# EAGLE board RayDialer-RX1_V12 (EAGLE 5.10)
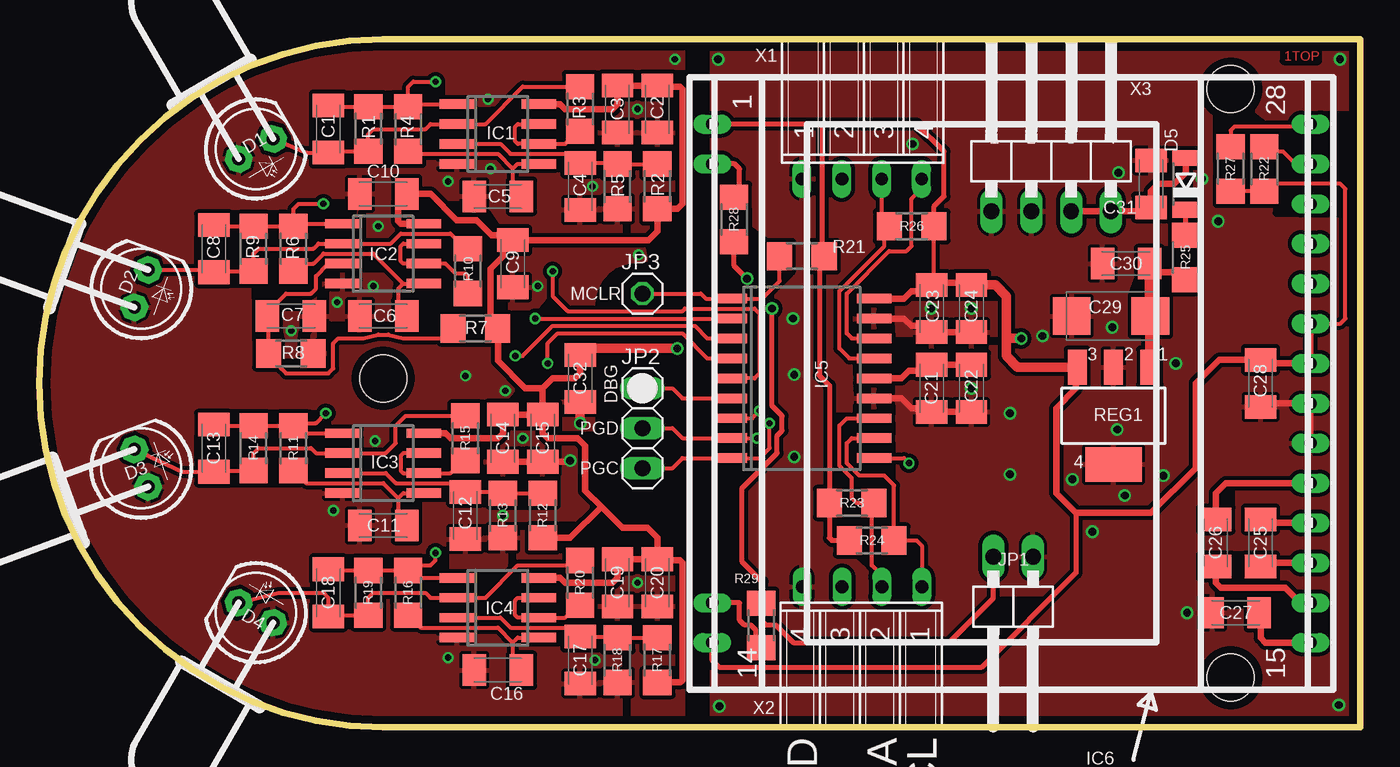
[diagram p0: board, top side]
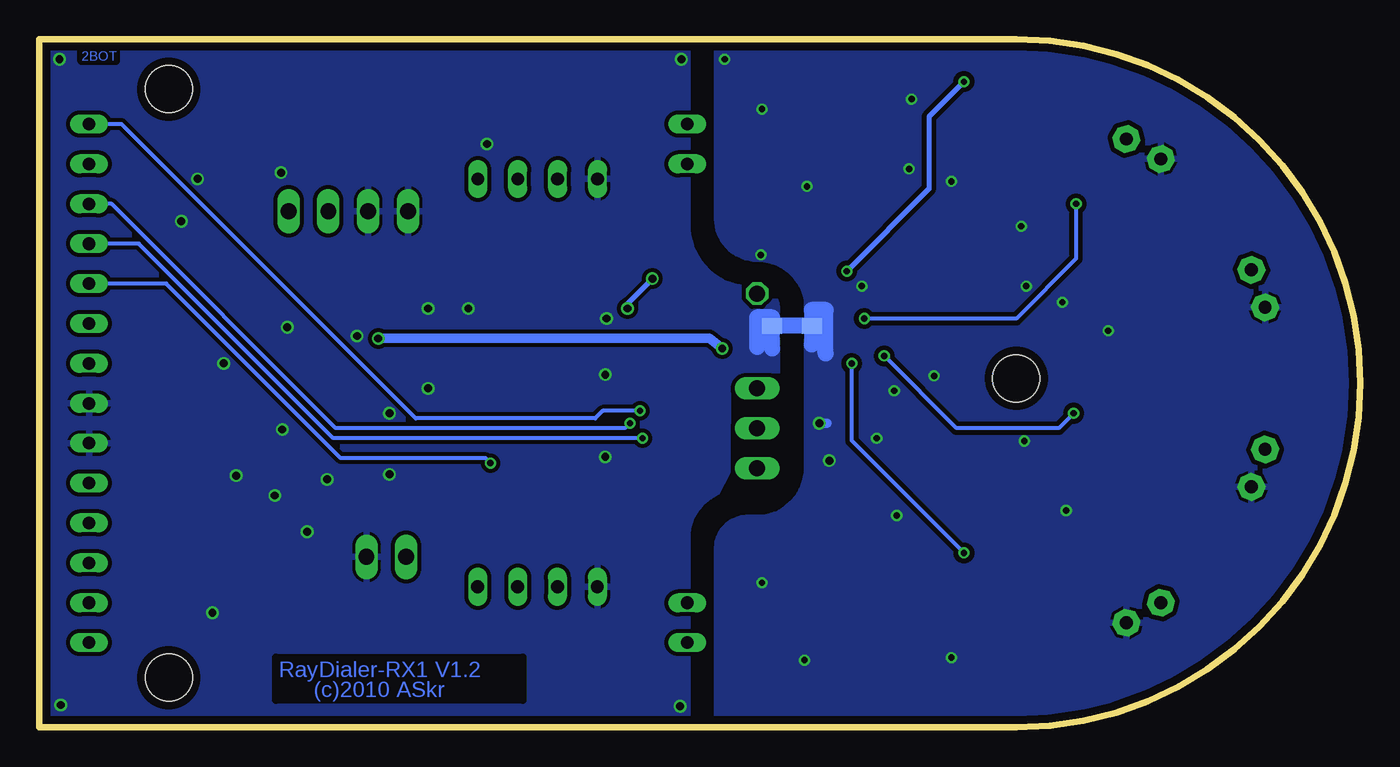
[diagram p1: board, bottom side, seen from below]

Size 84.14 x 43.81 mm. Coordinates in mm from the lower left corner, seen from the top.
Outline: 21.91,0 84.14,0 84.14,43.81 21.91,43.81 arc180 21.91,0
Copper layers (1*16): Top 0.035mm / dielectric 1.5mm / Bottom 0.035mm
Design rules "pcb-pool-2009": minimum track width 6mil, minimum drill 12mil, track to track 6mil, track to pad 6mil, pad to pad 6mil, via to via 6mil, smd to smd 6mil, copper to edge 20mil, drill to drill 8mil, minimum pad ring 8mil, minimum via ring 6mil, stop-mask expansion 3mil, vias tented up to drill 0mil, thermal gap 8mil
Holes 3 mm at 21.91,22.23 75.88,3.17 75.88,40.64
tRestrict: 111 lines
bRestrict: 11 lines

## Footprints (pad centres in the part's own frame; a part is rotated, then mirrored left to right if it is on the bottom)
C1206K = smd 1.5 x 2: 1 -1.5,0; 2 1.5,0
SMC_C = smd 2.4 x 2.4: + -2.5,0; - 2.5,0
AKKI_PHOTODIODE5MM = drill 0.813 pad 1.676 octagon: A -1.27,0; K 1.27,0
SOD80-R = smd 1 x 1.7: A 1.65,0; C -1.65,0
SO08 = smd 0.6 x 2.2: 1 -1.905,-2.6; 2 -0.635,-2.6; 3 0.635,-2.6; 4 1.905,-2.6; 5 1.905,2.6; 6 0.635,2.6; 7 -0.635,2.6; 8 -1.905,2.6
AKKI_SO18W = smd 0.6 x 2.2: 1 -5.715,-4.6; 2 -4.445,-4.6; 3 -3.175,-4.6; 4 -1.905,-4.6; 5 -0.635,-4.6; 6 0.635,-4.6; 7 1.905,-4.6; 8 3.175,-4.6; 9 4.445,-4.6; 10 4.445,4.6; 11 3.175,4.6; 12 1.905,4.6; 13 0.635,4.6; 14 -0.635,4.6; 15 -1.905,4.6; 16 -3.175,4.6; 17 -4.445,4.6; 18 -5.715,4.6
AKKI_EA_DOGS102 = drill 0.8 long: 1 -16.51,-19.05; 2 -13.97,-19.05; 13 13.97,-19.05; 14 16.51,-19.05; 15 16.51,19.05; 16 13.97,19.05; 17 11.43,19.05; 18 8.89,19.05; 19 6.35,19.05; 20 3.81,19.05; 21 1.27,19.05; 22 -1.27,19.05; 23 -3.81,19.05; 24 -6.35,19.05; 25 -8.89,19.05; 26 -11.43,19.05; 27 -13.97,19.05; 28 -16.51,19.05
1X02/90 = drill 1.016 long: 1 -1.27,-3.81; 2 1.27,-3.81
1X03 = drill 1.016 long: 1 -2.54,0; 2 0,0; 3 2.54,0
1X01 = drill 1.016 octagon: 1 0,0
R1206 = smd 1.6 x 1.803: 1 -1.422,0; 2 1.422,0
AKKI_SOT223_4PIN = smd 1.219 x 2.235: 1 -2.311,-3.099; 2 0,-3.099; 3 2.311,-3.099 | smd 3.6 x 2.2: 4 0,3.099
AKKI_GNDCON40 = smd 1.27 x 1.016: P$1 -1.27,0; P$2 1.27,0
AKKI_FH1X4 = drill 0.813 long: 1 -5.08,0; 2 -2.54,0; 3 0,0; 4 2.54,0
1X04/90 = drill 1.016 long: 1 -3.81,-3.81; 2 -1.27,-3.81; 3 1.27,-3.81; 4 3.81,-3.81

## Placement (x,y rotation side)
C1  1p  [C1206K]  18.41,38.1 90 top
C2  1u  [C1206K]  39.37,39.37 90 top
C3  100n  [C1206K]  36.83,39.37 90 top
C4  1u  [C1206K]  34.45,34.45 270 top
C5  10u  [C1206K]  29.21,33.81 180 top
C6  10u  [C1206K]  21.91,26.19 180 top
C7  1u  [C1206K]  16.03,26.19 0 top
C8  1p  [C1206K]  11.11,30.48 90 top
C9  100n  [C1206K]  30.16,29.53 90 top
C10  1u  [C1206K]  21.91,33.97 0 top
C11  10u  [C1206K]  21.91,12.86 180 top
C12  1u  [C1206K]  27.15,13.49 270 top
C13  1p  [C1206K]  11.11,17.78 90 top
C14  100n  [C1206K]  29.53,18.41 90 top
C15  1u  [C1206K]  32.07,18.41 90 top
C16  10u  [C1206K]  29.21,3.65 180 top
C17  1u  [C1206K]  34.45,4.29 270 top
C18  1p  [C1206K]  18.41,8.57 90 top
C19  100n  [C1206K]  36.83,9.21 90 top
C20  1u  [C1206K]  39.37,9.21 90 top
C21  10u  [C1206K]  56.83,21.59 270 top
C22  100n  [C1206K]  59.37,21.59 270 top
C23  1u  [C1206K]  56.83,26.67 270 top
C24  100n  [C1206K]  59.37,26.67 270 top
C25  1u  [C1206K]  77.79,11.75 90 top
C26  1u  [C1206K]  74.93,11.75 90 top
C27  1u  [C1206K]  76.2,7.3 180 top
C28  1u  [C1206K]  77.79,21.91 270 top
C29  22u;6V3  [SMC_C]  68.26,26.19 180 top
C30  100n  [C1206K]  69.22,29.53 180 top
C31  100n  [C1206K]  70.8,34.61 90 top
C32  100n  [C1206K]  34.45,22.23 270 top
D1  SFH203FA  [AKKI_PHOTODIODE5MM]  13.8,36.83 30 top
D2  SFH203FA  [AKKI_PHOTODIODE5MM]  6.5,27.94 70 top
D3  SFH203FA  [AKKI_PHOTODIODE5MM]  6.5,16.51 110 top
D4  SFH203FA  [AKKI_PHOTODIODE5MM]  13.8,7.3 150 top
D5  LL103  [SOD80-R]  73.03,34.61 90 top
IC1  MCP602SN  [SO08]  29.21,37.78 270 top
IC2  MCP602SN  [SO08]  21.91,30.16 270 top
IC3  MCP602SN  [SO08]  21.91,16.83 270 top
IC4  MCP602SN  [SO08]  29.21,7.62 270 top
IC5  DSPIC33FJ12GP201  [AKKI_SO18W]  48.58,21.59 270 top
IC6  EA_DOGS102  [AKKI_EA_DOGS102]  61.91,21.91 270 top
JP1  [1X02/90]  62.03,7.04 180 top
JP2  [1X03]  38.42,19.05 270 top
JP3  [1X01]  38.42,27.62 0 top
R1  4M7  [R1206]  20.95,38.1 270 top
R2  100k  [R1206]  39.37,34.45 270 top
R3  22k  [R1206]  34.45,39.37 270 top
R4  1M  [R1206]  23.49,38.1 90 top
R5  100k  [R1206]  36.83,34.45 90 top
R6  1M  [R1206]  16.19,30.48 90 top
R7  100k  [R1206]  27.78,25.4 0 top
R8  100k  [R1206]  16.03,23.81 180 top
R9  4M7  [R1206]  13.65,30.48 270 top
R10  22k  [R1206]  27.3,29.05 270 top
R11  1M  [R1206]  16.19,17.78 90 top
R12  100k  [R1206]  32.07,13.49 270 top
R13  100k  [R1206]  29.53,13.49 90 top
R14  4M7  [R1206]  13.65,17.78 270 top
R15  22k  [R1206]  27.15,18.42 270 top
R16  1M  [R1206]  23.49,8.57 90 top
R17  100k  [R1206]  39.37,4.29 270 top
R18  100k  [R1206]  36.83,4.29 90 top
R19  4M7  [R1206]  20.95,8.57 270 top
R20  22k  [R1206]  34.45,9.21 270 top
R21  10k  [R1206]  48.58,30 0 top
R22  10k  [R1206]  78.03,35.56 90 top
R23  82k  [R1206]  51.75,14.29 180 top
R24  82k  [R1206]  53.02,11.91 180 top
R25  1E  [R1206]  73.03,29.92 90 top
R26  100k  [R1206]  55.56,31.91 180 top
R27  100k  [R1206]  75.88,35.56 270 top
R28  100E  [R1206]  44.25,32.35 90 top
R29  100E  [R1206]  45.98,6.49 270 top
REG1  MCP1703-33  [AKKI_SOT223_4PIN]  68.42,19.84 180 top
W1  GNDCON  [AKKI_GNDCON40]  36.2,25.56 180 bottom
X1  [AKKI_FH1X4]  53.66,34.92 0 top
X2  [AKKI_FH1X4]  51.13,8.96 180 top
X3  [1X04/90]  64.45,36.67 0 top

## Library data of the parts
C1-C28 C30-C32 = rcl
C29 = rcl; SIZE: "C"; TYPE: TANT
D1-D5 IC5 IC6 R1-R29 REG1 W1 X1 X2 = Akki
IC1-IC4 = linear
JP1-JP3 X3 = pinhead

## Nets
+3V3: C2.2 C3.2 C9.2 C10.2 C14.2 C15.2 C19.2 C20.2 C23.1 C24.1 C28.1 C32.1 IC1.8 IC2.8 IC3.8 IC4.8 IC5.18 IC6.1 IC6.14 IC6.22 IC6.23 R2.2 R7.2 R12.2 R17.2 R21.2 R22.1 R23.2 R24.2 R26.1 R27.2 REG1.3
AGND: C2.1 C3.1 C4.2 C5.2 C6.2 C7.2 C9.1 C10.1 C11.2 C12.2 C14.1 C15.1 C16.2 C17.2 C19.1 C20.1 C32.2 D1.A D2.A D3.A D4.A IC1.4 IC2.4 IC3.4 IC4.4 R5.1 R8.1 R13.1 R18.1 W1.P$1
CD: IC5.9 IC6.26 JP2.3
CH1: C18.2 IC4.1 IC5.4 R16.2 R19.1
CH2: C13.2 IC3.1 IC5.3 R11.2 R14.1
CH3: C8.2 IC2.1 IC5.2 R6.2 R9.1
CH4: C1.2 IC1.1 IC5.5 R1.1 R4.2
CS0: IC5.7 IC6.28 R27.1
GND: C21.2 C22.2 C23.2 C24.2 C27.2 C28.2 C29.- C30.2 C31.2 IC5.13 IC5.17 IC6.20 IC6.21 JP1.1 REG1.2 REG1.4 W1.P$2 X1.1 X2.4 X3.1 X3.2
N$1: IC6.27 R22.2
N$2: IC6.13 R29.2
N$3: C21.1 C22.1 IC5.14
N$4: IC5.1 JP3.1 R21.1
N$5: C27.1 IC6.15
N$6: C25.1 IC6.17
N$7: C25.2 IC6.18
N$8: C26.2 IC6.19
N$9: C26.1 IC6.16
N$10: IC5.6 JP2.1
N$11: D5.C R25.2
N$12: IC6.2 R28.2
N$13: C29.+ C30.1 R25.1 REG1.1
N$14: JP1.2 R28.1 R29.1
N$15: C31.1 D5.A X3.3 X3.4
RX: IC5.15 R26.2 X1.3
SCK: IC5.8 IC6.25 JP2.2
SCL: IC5.11 R24.1 X2.1
SDA: IC5.12 R23.1 X2.2
SO: IC5.10 IC6.24
TX: IC5.16 X1.4
UN: C1.1 D1.K IC1.2 R1.2 R3.1
UN1: C8.1 D2.K IC2.2 R9.2 R10.1
UN2: C13.1 D3.K IC3.2 R14.2 R15.1
UN3: C18.1 D4.K IC4.2 R19.2 R20.1
UO2: IC1.6 IC1.7 R3.2
UO4: IC2.6 IC2.7 R10.2
UO6: IC3.6 IC3.7 R15.2
UO8: IC4.6 IC4.7 R20.2
UP: C4.1 IC1.3 R2.1 R5.2
UP1: C6.1 IC2.5 R6.1
UP2: C5.1 IC1.5 R4.1
UP3: C7.1 IC2.3 R7.1 R8.2
UP4: C11.1 IC3.5 R11.1
UP5: C12.1 IC3.3 R12.1 R13.2
UP6: C16.1 IC4.5 R16.1
UP7: C17.1 IC4.3 R17.1 R18.2

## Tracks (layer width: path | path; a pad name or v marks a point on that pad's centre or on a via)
+3V3  (via drill 0.5, 0.5 pad 0.5)
  Top 0.254: R26.1 56.98,28.32 C23.1 | IC6.23 82.87,25.72 83.18,26.04 83.18,34.29 82.87,34.61 78.5,34.61 R22.1 R27.2 | R27.2
  Top 0.305: R24.2 50.48,11.91 50.32,12.06 R23.2 50.33,21.76 49.69,22.4 49.69,29.37 50,29.68 | 49.85,38.42 55.88,38.42 57.63,36.67 57.63,33.81 56.99,33.18 R26.1 | 49.85,38.42 IC6.1 | IC6.14 42.86,4.29 43.34,3.81 60.01,3.81 66.04,9.84 66.04,13.65 | 50,29.68 R21.2 | 50,29.68 49.85,29.83 49.85,38.42
  Top 0.406: IC1.8 33.18,39.69 33.5,39.37 36.51,39.37 36.83,39.69 C3.2 C2.2 39.44,40.8 40.8,40.8 40.96,40.64 40.96,33.34 40.65,33.03 R2.2 | 29.81,31.2 29.53,31.34 28.82,31.34 27.86,32.31 26.59,32.31 24.92,33.97 C10.2 22.86,33.42 22.86,32.23 23.02,32.07 IC2.8 | 29.81,31.2 C9.2 38.81,31.03 39.37,31.59 R2.2 | IC3.8 25.88,18.73 26.19,18.41 29.21,18.41 29.53,18.73 C14.2 | C14.2 | C15.2 C14.2 | IC4.8 33.18,9.53 33.5,9.21 36.51,9.21 36.83,9.53 C19.2 C20.2 | IC5.18 55.09,27.3 55.56,27.78 56.44,27.78 C23.1 | 56.98,28.32 59.22,28.32 C24.1 | IC6.23 IC6.22 78.02,23.18 C28.1 75.16,23.41 73.66,21.91 73.66,16.51 70.8,13.65 66.04,13.65 64.77,14.92 64.77,20.32 66.04,21.59 66.04,23.35 REG1.3 | R17.2 40.81,2.86 40.96,3.02 40.96,10.48 40.8,10.64 39.44,10.64 C20.2 | C20.2 39.37,12.06 38.74,12.7 37.15,12.7 35.8,14.05 | 35.8,14.05 34.77,15.08 34.77,17.94 34.29,18.41 32.39,18.41 32.07,18.73 C15.2 | C15.2 32.14,19.84 | C15.2 32.07,21.59 | 32.07,21.59 30.96,21.59 29.21,23.34 R7.2 28.73,25.87 28.73,29.21 29.53,30 29.53,30.64 29.81,30.92 29.81,31.2 | R2.2 | C15.2 | 32.07,21.59 32.7,22.23 34.13,22.23 34.45,22.54 C32.1 | R12.2 33.82,12.07 35.8,14.05
  Top 0.61: C24.1 60.89,28.17 61.6,27.46 61.6,24.77 | v62.55,24.77 61.6,24.77 | v40.64,24.13 34.7,24.13 arc90 C32.1 | 61.6,24.77 61.6,23.65 62.31,22.94 REG1.3
  Bottom 0.61: v62.55,24.77 41.43,24.77 v40.64,24.13
AGND  (via drill 0.4 pad 0.5, 0.5 pad 0.5)
  Top 0.406: v33.81,16.99 33.74,16.91 C15.1 C14.1
  Top 0.61: v34.45,19.37 C32.2
  Bottom 0.406: v33.81,16.99 33.81,17.14
  Bottom 0.61: v34.45,19.37 33.97,19.37
  Bottom 1.016: 34.92,24.37 W1.P$1 34.92,26.59 34.05,26.59 34.05,23.81
  other vias: 38.1,9.21 26.03,4.45 35.4,4.29 18.73,13.81 21.27,28.1 29.69,21.43 27.15,22.38 21.39,18.24 26.03,34.77 38.1,39.37 35.24,34.45 31.75,28.1 30.8,18.41 29.53,13.49 21.59,31.91 28.73,35.56 40.48,42.55 28.57,40.01 18.97,27.07 38.18,30.08 16.05,25.26
  pour Bottom (isolate 0.305): 40.96,45.09 40.96,32.38 arc-90 38.42,29.84 arc77 35.24,27.3 35.24,16.51 arc90 38.42,13.34 39.05,13.34 arc-90 40.96,11.43 40.96,-1.27 -2.86,-1.27 -2.86,45.09
  pour Top (isolate 0.254): 40.96,45.09 40.96,33.02 arc-90 39.05,29.84 38.1,29.69 arc90 35.24,26.99 35.24,15.88 37.78,13.34 39.05,13.34 40.96,11.43 40.96,-1.27 -1.59,-1.27 -1.59,45.09
CD  (via drill 0.4)
  Top 0.254: v46.51,19.37 46.51,17.78 45.88,17.14 IC5.9 40.96,17.14 40.32,16.51 JP2.3
  Bottom 0.254: v46.51,19.37 46.83,19.05 65.25,19.05 79.53,33.34 IC6.26
CH1  (via drill 0.4)
  Top 0.254: C18.2 18.49,9.99 R19.1 R16.2 | R16.2 23.96,9.53 IC4.1 | IC5.4 42.54,23.5 40.96,25.08 33.02,25.08 32.39,24.45 v32.39,23.18 | v25.24,11.11 25.24,10.64 24.92,10.32 23.82,10.32 R16.2
  Bottom 0.254: v32.39,23.18 32.39,18.26 v25.24,11.11
CH2  (via drill 0.4)
  Top 0.254: C13.2 11.19,19.2 R14.1 R11.2 | R11.2 16.66,18.73 IC3.1 | IC5.3 42.55,24.77 41.75,25.56 32.7,25.56 30.8,23.65 v30.32,23.65 | v18.26,20 17.62,19.37 16.36,19.37 R11.2
  Bottom 0.254: v30.32,23.65 25.72,19.05 19.21,19.05 v18.26,20
CH3  (via drill 0.4)
  Top 0.254: R6.2 16.66,32.07 IC2.1 | R6.2 R9.1 11.19,31.9 C8.2 | v31.59,26.04 IC5.2 | v18.1,33.34 16.51,33.34 16.19,33.02 R6.2
  Bottom 0.254: v18.1,33.34 18.1,29.84 21.91,26.04 v31.59,26.04
CH4  (via drill 0.4)
  Top 0.254: C1.2 18.49,39.52 R1.1 R4.2 | R4.2 23.33,39.69 IC1.1 | IC5.5 45.56,22.23 45.88,22.54 45.88,26.35 45.56,26.67 41.12,26.67 40.96,26.51 33.65,26.51 32.7,27.46 v32.7,29.05 | v25.24,41.12 23.81,41.12 23.49,40.8 R4.2
  Bottom 0.305: v32.7,29.05 27.46,34.29 27.46,38.89 v25.24,41.12
CS0  (via drill 0.4)
  Top 0.254: IC5.7 45.4,19.68 v45.88,20.16 | R27.1 75.88,38.02 76.12,38.26 80.8,38.26 IC6.28
  Bottom 0.254: v45.88,20.16 48.26,20.16 48.74,19.68 60.17,19.68 78.9,38.42 IC6.28
GND  (via drill 0.5 pad 0.5)
  Top 0.406: C23.2 56.76,25.24 | C23.2 C24.2 | IC5.13 54.93,20.95 55.56,20.32 56.6,20.32 C21.2 C22.2 | IC5.17 55.09,26.04 55.56,25.56 56.44,25.56 C23.2 | C28.2 78.02,20.64 IC6.21 IC6.20
  Bottom 1.016: 37.46,24.13 W1.P$2 37.46,26.11 38.42,26.11 38.42,24.21
  other vias: 59.37,26.67 59.37,21.59 61.83,20 63.9,24.92 68.34,25.48 72.39,23.18 61.83,16.11 73.1,7.3 56.81,26.67 68.66,18.97 65.8,15.8 69.14,14.76 71.6,16.03 67.07,12.46 48,26.04 48.08,22.46 48.08,17.22 43.24,42.55 82.85,42.55 82.77,1.43 43.32,1.35 74.06,34.92 75.09,32.23 55.62,37.15 68.74,35.32
  pour Bottom (isolate 0.254): 42.86,43.18 83.5,43.18 83.5,0.64 42.86,0.64 42.86,12.06 arc90 39.69,15.24 39.05,15.24 arc-90 37.15,17.14 37.15,26.67 arc-90 38.42,27.94 arc90 42.86,31.75
  pour Top (isolate 0.254): 83.5,43.18 42.86,43.18 42.86,32.38 arc-90 38.42,27.94 37.78,27.94 arc90 37.15,27.3 37.15,17.14 arc90 39.05,15.24 39.69,15.24 arc-90 42.86,12.06 42.86,0.64 83.5,0.64
N$1
  Top 0.254: IC6.27 80.01,35.88 79.22,36.67 78.34,36.67 R22.2
N$2
  Top 0.305: IC6.13 44.61,7.94 44.61,6.83 44.93,6.51 45.32,6.51 45.64,6.19 45.64,5.4 R29.2 46.04,5.13
N$3
  Top 0.406: IC5.14 54.93,22.23 55.4,22.7 56.44,22.7 C21.1 C22.1
N$4
  Top 0.254: R21.1 47.15,29.84 47.15,28.42 46.04,27.3 IC5.1 42.47,27.3 42.15,27.62 JP3.1 | JP3.1
N$5
  Top 0.406: IC6.15 78.1,5.4 77.79,5.71 77.79,7.21 C27.1
N$6
  Top 0.406: IC6.17 78.02,10.48 C25.1
N$7
  Top 0.406: IC6.18 78.02,13.02 C25.2
N$8
  Top 0.406: IC6.19 75.56,15.56 74.93,14.92 C26.2
N$9
  Top 0.406: IC6.16 80.33,7.94 79.37,8.89 75.25,8.89 74.93,9.21 C26.1
N$10
  Top 0.254: IC5.6 40.96,20.95 40.32,21.59 JP2.1
N$11
  Top 0.305: R25.2 D5.C | R25.2
N$12
  Top 0.305: IC6.2 44.29,35.88 44.61,35.56 44.61,34.12 R28.2
N$13
  Top 0.406: R25.1 72.78,28.5 72.31,28.97 70.71,28.97
  Top 0.61: C30.1 70.71,28.97 70.71,26.72 C29.+ 70.73,26.64 REG1.1
N$14  (via drill 0.5 pad 0.5)
  Top 0.305: R28.1 44.25,29.41 v45.09,28.57 | v46.67,26.67 46.67,20.48 47.31,19.84 47.31,18.89 46.99,18.57 46.99,17.46 44.77,15.24 44.77,10.56 46.04,9.29 46.04,7.97 | JP1.2 60.76,8.21 57.94,5.4 48.02,5.4 46.91,6.51 46.28,6.51 46.04,6.75 46.04,7.97 | 45.63,8.26 R29.1 46.04,7.97
  Bottom 0.305: v45.09,28.57 46.67,26.99 v46.67,26.67
N$15
  Top 0.305: 70.56,32.86 C31.1 | D5.A
  Top 0.406: X3.3 X3.4 70.56,32.86 | C31.1 70.8,34.13 71.28,34.61 72.31,34.61 73.03,35.32 D5.A
RX
  Top 0.254: IC5.15 51.59,23.5 50.96,24.13 50.96,27.78 53.82,30.64 53.82,31.59 R26.2 53.66,31.91 X1.3
SCK  (via drill 0.4)
  Top 0.254: v45.72,18.41 IC5.8 40.96,18.41 40.32,19.05 JP2.2
  Bottom 0.254: v45.72,18.41 65.4,18.41 77.79,30.8 IC6.25
SCL
  Top 0.254: X2.1 56.21,11.57 55.88,11.91 R24.1 54.44,15.41 53.82,16.03 52.23,16.03 51.43,16.83 51.43,18.1 51.75,18.41 IC5.11
SDA
  Top 0.254: X2.2 53.67,9.67 53.02,10.32 53.02,14.14 R23.1 52.07,14.29 51.75,14.61 51.75,15.88 50.96,16.67 50.96,19.21 51.43,19.68 IC5.12
SO  (via drill 0.4)
  Top 0.254: IC5.10 55.09,17.14 v55.4,16.83
  Bottom 0.254: v55.4,16.83 55.72,17.14 64.93,17.14 76.04,28.26 IC6.24
TX
  Top 0.254: IC5.16 51.75,24.77 51.43,25.08 51.43,27.62 54.13,30.32 55.24,30.32 55.56,30.64 55.56,33.66 56.2,34.29 X1.4
UN
  Top 0.254: D1.K 17.03,36.6 C1.1 18.49,36.68 R1.2 20.96,37.78 21.27,38.1 24.61,38.1 24.92,38.42 IC1.2 28.42,38.42 30.79,40.79 R3.1
UN1
  Top 0.254: D2.K 10.96,29.13 C8.1 11.19,29.06 R9.2 13.65,30.16 13.97,30.48 17.46,30.48 17.78,30.8 IC2.2 22.38,30.8 23.02,31.43 26.19,31.43 26.99,30.64 27.14,30.64 R10.1
UN2
  Top 0.254: D3.K 9.1,16.28 C13.1 11.19,16.36 R14.2 13.65,17.46 13.97,17.78 17.3,17.78 17.62,17.46 IC3.2 22.07,17.46 22.7,18.1 22.7,19.21 23.34,19.84 R15.1
UN3
  Top 0.254: 26.35,8.26 24.92,8.26 24.61,8.57 21.27,8.57 20.96,8.26 R19.2 18.49,7.15 C18.1 18.42,8.26 18.1,8.57 15.24,8.57 D4.K | 26.35,8.26 IC4.2 | R20.1 34.14,10.32 30.48,10.32 28.42,8.26 26.35,8.26 | 26.35,8.26
UO2
  Top 0.254: IC1.7 30.48,38.42 30.32,38.26 30.32,37.31 30.48,37.15 IC1.6 33.5,37.15 33.65,37.31 33.81,37.31 R3.2
UO4
  Top 0.254: IC2.7 23.18,30.8 23.02,30.64 23.02,29.69 23.18,29.53 IC2.6 25.88,29.53 26.51,28.89 27.15,28.89 27.3,28.73 R10.2
UO6
  Top 0.254: IC3.7 23.18,17.46 23.02,17.3 23.02,16.35 23.18,16.19 IC3.6 26.19,16.19 26.35,16.35 26.5,16.35 R15.2
UO8
  Top 0.254: IC4.7 30.48,8.26 30.32,8.1 30.32,7.14 30.48,6.99 IC4.6 33.5,6.99 33.65,7.14 33.81,7.14 R20.2
UP
  Top 0.254: IC1.3 29.37,37.15 30,36.51 33.89,36.51 C4.1 36.75,35.95 R5.2 R2.1 | R2.1
UP1
  Top 0.254: 23.18,28.26 IC2.5 | 23.18,28.26 21.27,30.16 18.1,30.16 17.46,29.53 16.66,29.53 R6.1 | 23.18,28.26 22.86,27.94 22.86,26.74 C6.1
UP2
  Top 0.254: IC1.5 30.48,35.88 30.16,35.56 | 30.16,35.56 30.16,34.36 C5.1 | 30.16,35.56 29.21,36.51 23.66,36.51 R4.1
UP3
  Top 0.254: IC2.3 18.42,29.53 17.62,28.73 17.62,27.94 17.3,27.62 15.72,27.62 14.92,26.83 14.92,26.58 C7.1 14.61,26.12 R8.2 15.08,23.34 15.08,23.18 15.4,22.86 | R7.1 26.36,25.25 25.88,24.77 23.18,24.77 22.23,25 21.59,25 20.64,24.77 19.05,24.77 18.73,24.45 18.73,22.86 18.42,22.54 15.72,22.54 15.4,22.86 | 15.4,22.86
UP4
  Top 0.254: IC3.5 23.18,14.92 22.86,14.61 | 22.86,14.61 22.86,13.41 C11.1 | 22.86,14.61 21.91,15.56 16.99,15.56 R11.1
UP5
  Top 0.254: IC3.3 22.07,16.19 22.7,15.56 26.58,15.56 C12.1 29.45,14.99 R13.2 R12.1 | R12.1
UP6
  Top 0.254: IC4.5 30.48,5.71 30.16,5.4 | 30.16,5.4 30.16,4.2 C16.1 | 30.16,5.4 29.21,6.35 24.3,6.35 R16.1
UP7
  Top 0.254: IC4.3 29.37,6.99 30,6.35 33.89,6.35 C17.1 36.75,5.79 R18.2 R17.1 | R17.1

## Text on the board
Top: 1TOP
Bottom: 2BOT | RayDialer-RX1 V1.2 | (c)2010 ASkr
tPlace: SERIAL | POWER | CH4 | GND | RX | TX | GND | GND | +UB | +UB | 1 | 2 | 3 | 4 | CH3 | MCLR | DBG | PGD | PGC | CH2 | GND | SDA | SCL | CH1 | I2C | BACKL. | V1.2
bPlace: V1.2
